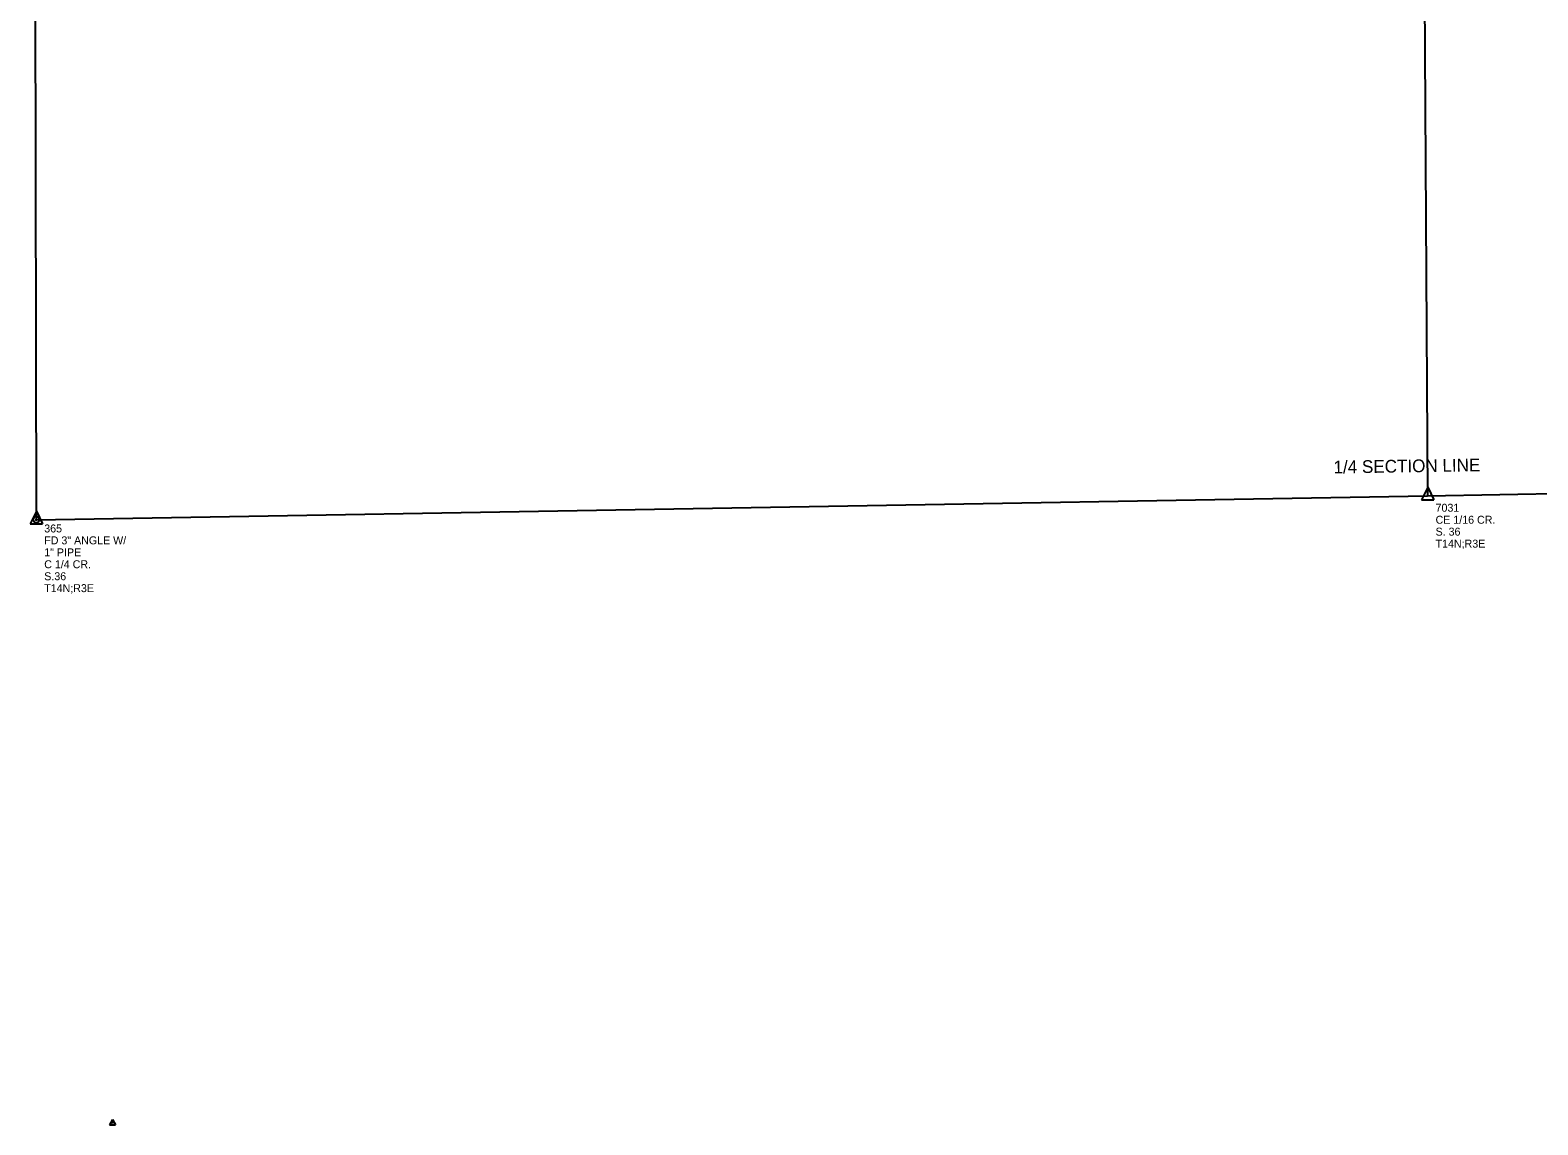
# Model space of a CAD drawing. Extents: x 1688544 to 1704497, y 535668 to 545444.
# Drawn here: x 1691156 to 1692576, y 535668 to 536698 of the extents above; entities that cross this region are included whole.
import ezdxf

# ---------------------------------------------------------------- set-up
doc = ezdxf.new("R2010")
doc.units = 0
for name, color, linetype in [('S_CAL_CORNER', 7, 'Continuous'), ('S_CAL_CORNER_ANNOT', 7, 'Continuous'), ('S_IRON_PIN', 7, 'Continuous'), ('S_IRON_PIN_ANNOT', 7, 'Continuous'), ('S_QSECTION', 7, 'Continuous'), ('S_SECONDARY_CTL', 7, 'Continuous'), ('S_SECTION_ANNOT', 7, 'Continuous'), ('S_SIXTEEN_SECTION', 7, 'Continuous')]:
    doc.layers.add(name, color=color, linetype=linetype)

msp = doc.modelspace()

# ---------------------------------------------------------------- linework, layer by layer
at = {"layer": 'S_CAL_CORNER'}
for p, q in [((1692472, 536267.9), (1692466.1, 536256)), ((1692472, 536267.9), (1692466.1, 536256)), ((1692472, 536267.9), (1692466.1, 536256)), ((1692472, 536267.9), (1692477.8, 536256)), ((1692472, 536267.9), (1692477.8, 536256)), ((1692472, 536267.9), (1692477.8, 536256)), ((1692466.1, 536256), (1692477.8, 536256)), ((1692466.1, 536256), (1692477.8, 536256)), ((1692466.1, 536256), (1692477.8, 536256)), ((1691162, 536245.4), (1691156.1, 536233.6)), ((1691162, 536245.4), (1691167.8, 536233.6)), ((1691156.1, 536233.6), (1691167.8, 536233.6))]:
    msp.add_line(p, q, dxfattribs=at)
at = {"layer": 'S_IRON_PIN'}
for radius in [2.91, 0.411, 0.262, 0.212, 0.145, 0.0822, 0.0581]:
    msp.add_circle((1691161.9, 536237.4), radius, dxfattribs=at)
at = {"layer": 'S_QSECTION'}
for p, q in [((1691159.5, 537556.8), (1691161.9, 536237.4)), ((1692471.9, 536259.9), (1693781.9, 536282.4)), ((1691161.9, 536237.4), (1692471.9, 536259.9))]:
    msp.add_line(p, q, dxfattribs=at)
at = {"layer": 'S_SECONDARY_CTL'}
for p, q in [((1691233.7, 535672.6), (1691230.7, 535667.7)), ((1691233.7, 535672.6), (1691236.6, 535667.7)), ((1691230.7, 535667.7), (1691236.6, 535667.7))]:
    msp.add_line(p, q, dxfattribs=at)
for radius in [0.311, 0.183, 0.103]:
    msp.add_circle((1691233.7, 535670), radius, dxfattribs=at)
at = {"layer": 'S_SIXTEEN_SECTION'}
msp.add_line((1692463.3, 537579.4), (1692471.9, 536259.9), dxfattribs=at)

# ---------------------------------------------------------------- texts
at = {"layer": 'S_CAL_CORNER_ANNOT'}
for s, p in [('7031', (1692479.4, 536244.9)), ('CE 1/16 CR. ', (1692479.4, 536233.6)), ('S. 36 ', (1692479.4, 536222.4)), ('T14N;R3E', (1692479.4, 536211.1))]:
    msp.add_text(s, height=7.5, dxfattribs=at).set_placement(p)
at = {"layer": 'S_IRON_PIN_ANNOT'}
for s, p in [('365', (1691169.4, 536225.4)), ('FD 3" ANGLE W/', (1691169.4, 536214.2)), ('1" PIPE ', (1691169.4, 536202.9)), ('C 1/4 CR.', (1691169.4, 536191.7)), ('S.36', (1691169.4, 536180.4)), ('T14N;R3E', (1691169.4, 536169.2))]:
    msp.add_text(s, height=7.5, dxfattribs=at).set_placement(p)
at = {"layer": 'S_SECONDARY_CTL'}
msp.add_text('TV', height=1.5, dxfattribs=at).set_placement((1691232.5, 535668))
at = {"layer": 'S_SECTION_ANNOT'}
msp.add_text('1/4 SECTION LINE', height=12, rotation=0.8773, dxfattribs=at).set_placement((1692383.4, 536280.9))

doc.saveas('drawing.dxf')
